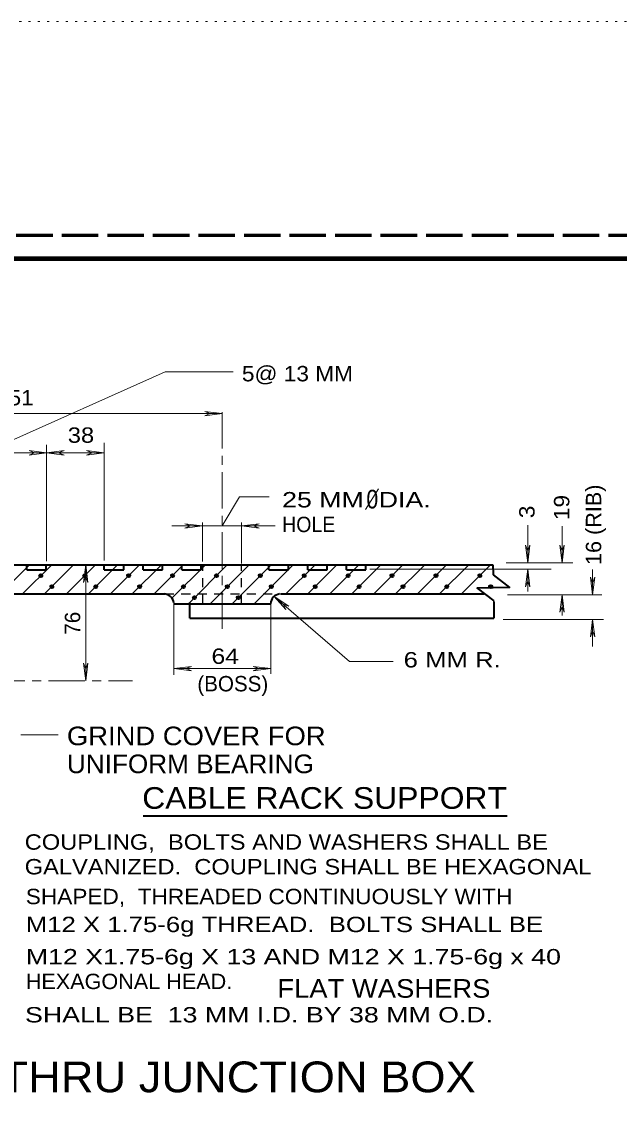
# Model space of a CAD drawing. Extents: x 312583 to 312854, y 144419 to 144597.
# Drawn here: x 312769.2 to 312798.7, y 144543.4 to 144596.8 of the extents above; entities that cross this region are included whole.
import ezdxf
from ezdxf.enums import TextEntityAlignment as Align

# ---------------------------------------------------------------- set-up
doc = ezdxf.new("R2010")
doc.units = 0
doc.header["$LTSCALE"] = 0.3
doc.header["$PDMODE"] = 32
doc.header["$PDSIZE"] = 0.15
for name, pattern in [('DOTTED', [1.5, 0.3, -1.2]), ('LONG_DASH_SHORT_DASH', [9.9, 6, -1.2, 1.5, -1.2]), ('LONG_DASHED', [7.5, 6, -1.5]), ('SHORT_DASHED', [2.7, 1.5, -1.2])]:
    doc.linetypes.add(name, pattern=pattern)
for name, color, linetype, lineweight in [('1', 7, 'Continuous', 40), ('2', 7, 'Continuous', 13), ('63', 7, 'DOTTED', 13)]:
    doc.layers.add(name, color=color, linetype=linetype, lineweight=lineweight)

msp = doc.modelspace()

# ---------------------------------------------------------------- linework, layer by layer
at = {"layer": '1', "linetype": 'LONG_DASHED', "lineweight": 60}
msp.add_line((312851.75, 144586.2246), (312583.526, 144586.2246), dxfattribs=at)
at = {"layer": '1', "lineweight": 13}
for p, q in [((312767.5099, 144575.5592), (312776.3113, 144579.4769)), ((312778.1436, 144571.8716), (312776.6333, 144571.8716)), ((312768.1769, 144568.5136), (312769.6106, 144569.9472)), ((312769.2426, 144568.4982), (312770.6993, 144569.9472)), ((312770.3313, 144568.4982), (312771.7803, 144569.9472)), ((312771.4199, 144568.5059), (312772.8613, 144569.9472)), ((312772.5009, 144568.5059), (312773.9499, 144569.9472)), ((312773.5896, 144568.5059), (312775.0309, 144569.9472)), ((312774.6783, 144568.5136), (312776.1196, 144569.9472)), ((312775.7669, 144568.5136), (312777.2006, 144569.9472)), ((312776.6563, 144568.3219), (312778.2893, 144569.9472)), ((312777.4843, 144568.0612), (312779.3703, 144569.9472)), ((312778.5576, 144568.0536), (312780.4513, 144569.9472)), ((312779.6386, 144568.0459), (312781.5399, 144569.9472)), ((312780.7119, 144568.0382), (312782.6209, 144569.9472)), ((312782.2683, 144568.5136), (312783.7096, 144569.9472)), ((312783.3493, 144568.5136), (312784.7906, 144569.9472)), ((312784.4379, 144568.5136), (312785.8793, 144569.9472)), ((312785.5189, 144568.5136), (312786.9603, 144569.9472)), ((312786.6076, 144568.5136), (312788.0413, 144569.9472)), ((312787.6886, 144568.5136), (312789.1299, 144569.9472)), ((312788.7696, 144568.5136), (312790.2109, 144569.9472)), ((312789.8583, 144568.5136), (312791.2996, 144569.9472)), ((312790.9393, 144568.5136), (312792.3806, 144569.9472)), ((312793.1473, 144570.0546), (312796.4516, 144570.0546))]:
    msp.add_line(p, q, dxfattribs=at)
at = {"layer": '1'}
for p, q in [((312769.4649, 144569.7096), (312769.4649, 144569.9472)), ((312770.4233, 144569.7096), (312770.4233, 144569.9472)), ((312773.2983, 144569.7096), (312773.2983, 144569.9472)), ((312774.2566, 144569.7096), (312774.2566, 144569.9472)), ((312775.2149, 144569.7096), (312775.2149, 144569.9472)), ((312776.1733, 144569.7096), (312776.1733, 144569.9472)), ((312777.1316, 144569.7096), (312777.1316, 144569.9472)), ((312778.0899, 144569.7096), (312778.0899, 144569.9472)), ((312781.4326, 144569.7096), (312781.4326, 144569.9472)), ((312782.3909, 144569.7096), (312782.3909, 144569.9472)), ((312783.3493, 144569.7096), (312783.3493, 144569.9472)), ((312784.3076, 144569.7096), (312784.3076, 144569.9472)), ((312785.2659, 144569.7096), (312785.2659, 144569.9472)), ((312786.2243, 144569.7096), (312786.2243, 144569.9472)), ((312792.4956, 144569.9472), (312792.5033, 144569.4566)), ((312777.5303, 144567.3176), (312777.5303, 144568.0919)), ((312792.5339, 144568.1456), (312792.5493, 144567.3176))]:
    msp.add_line(p, q, dxfattribs=at)
at = {"layer": '1', "lineweight": 158}
msp.add_lwpolyline([(312616.5, 144423.1446), (312616.5, 144585.0846), (312849, 144585.0846)], dxfattribs=at)
at = {"layer": '1'}
for p in [(312770.1626, 144569.4182), (312772.3323, 144569.4182), (312774.5019, 144569.4182), (312776.6716, 144569.4182), (312778.8413, 144569.4182), (312781.0033, 144569.4182), (312783.1729, 144569.4182), (312785.3426, 144569.4182), (312787.5123, 144569.4182), (312789.6819, 144569.4182), (312791.8516, 144569.4182), (312770.7069, 144568.8739), (312772.8766, 144568.8739), (312775.0463, 144568.8739), (312777.2083, 144568.8739), (312779.3779, 144568.8739), (312781.5476, 144568.8739), (312783.7173, 144568.8739), (312785.8869, 144568.8739), (312788.0566, 144568.8739), (312790.2186, 144568.8739), (312792.3883, 144568.8739), (312777.7526, 144568.3296), (312779.9223, 144568.3296)]:
    msp.add_point(p, dxfattribs=at)
at = {"layer": '2'}
for p, q in [((312779.6616, 144579.4769), (312776.3113, 144579.4769)), ((312760.2113, 144577.4222), (312779.1249, 144577.4222)), ((312778.2586, 144577.5296), (312778.5346, 144577.4222)), ((312779.1249, 144577.4222), (312778.2586, 144577.5296)), ((312778.2586, 144577.3149), (312778.5346, 144577.4222)), ((312779.1249, 144577.4222), (312778.2586, 144577.3149)), ((312770.4463, 144570.1236), (312770.4463, 144575.8736)), ((312773.2906, 144570.1619), (312773.2906, 144575.9809)), ((312765.7083, 144575.4826), (312770.4463, 144575.4826)), ((312769.5799, 144575.5899), (312769.8559, 144575.4826)), ((312770.4463, 144575.4826), (312769.5799, 144575.5899)), ((312769.5799, 144575.3752), (312769.8559, 144575.4826)), ((312770.4463, 144575.4826), (312769.5799, 144575.3752)), ((312770.4463, 144575.4826), (312771.3126, 144575.5899)), ((312770.4463, 144575.4826), (312773.2906, 144575.4826)), ((312770.4463, 144575.4826), (312771.3126, 144575.3752)), ((312771.3126, 144575.5899), (312771.0366, 144575.4826)), ((312771.3126, 144575.3752), (312771.0366, 144575.4826)), ((312772.4243, 144575.5899), (312772.7003, 144575.4826)), ((312773.2906, 144575.4826), (312772.4243, 144575.5899)), ((312772.4243, 144575.3752), (312772.7003, 144575.4826)), ((312773.2906, 144575.4826), (312772.4243, 144575.3752)), ((312786.2087, 144572.6833), (312786.845, 144573.7107)), ((312777.2773, 144571.9789), (312777.5533, 144571.8716)), ((312778.1436, 144571.8716), (312777.2773, 144571.9789)), ((312778.1436, 144570.1082), (312778.1436, 144572.0479)), ((312780.0833, 144570.0162), (312780.0833, 144572.0479)), ((312780.0833, 144571.8716), (312780.9496, 144571.9789)), ((312780.9496, 144571.9789), (312780.6736, 144571.8716)), ((312794.2206, 144570.0546), (312794.2206, 144571.9089)), ((312777.2773, 144571.7642), (312777.5533, 144571.8716)), ((312778.1436, 144571.8716), (312777.2773, 144571.7642)), ((312778.1436, 144571.8716), (312780.0833, 144571.8716)), ((312780.0833, 144571.8716), (312781.7393, 144571.8716)), ((312780.0833, 144571.8716), (312780.9496, 144571.7642)), ((312780.9496, 144571.7642), (312780.6736, 144571.8716)), ((312795.9149, 144570.0546), (312795.9149, 144571.8557)), ((312794.1133, 144570.9209), (312794.2206, 144570.6449)), ((312794.2206, 144570.0546), (312794.1133, 144570.9209)), ((312794.3279, 144570.9209), (312794.2206, 144570.6449)), ((312794.2206, 144570.0546), (312794.3279, 144570.9209)), ((312795.8076, 144570.9209), (312795.9149, 144570.6449)), ((312795.9149, 144570.0546), (312795.8076, 144570.9209)), ((312796.0223, 144570.9209), (312795.9149, 144570.6449)), ((312795.9149, 144570.0546), (312796.0223, 144570.9209)), ((312772.3783, 144569.9472), (312772.2709, 144569.0809)), ((312772.3783, 144569.9472), (312772.3783, 144564.2202)), ((312772.3783, 144569.9472), (312772.4856, 144569.0809)), ((312772.2709, 144569.0809), (312772.3783, 144569.3569)), ((312772.4856, 144569.0809), (312772.3783, 144569.3569)), ((312786.4236, 144569.7326), (312795.3706, 144569.7326)), ((312794.2206, 144569.7326), (312794.1133, 144568.8662)), ((312794.2206, 144568.6362), (312794.2206, 144569.7326)), ((312794.2206, 144569.7326), (312794.3279, 144568.8662)), ((312797.3103, 144569.3416), (312797.4176, 144569.0656)), ((312797.4176, 144568.4752), (312797.3103, 144569.3416)), ((312797.4176, 144568.4752), (312797.4176, 144569.7172)), ((312797.5249, 144569.3416), (312797.4176, 144569.0656)), ((312797.4176, 144568.4752), (312797.5249, 144569.3416)), ((312794.1133, 144568.8662), (312794.2206, 144569.1422)), ((312794.3279, 144568.8662), (312794.2206, 144569.1422)), ((312781.6856, 144568.3909), (312782.2683, 144567.7392)), ((312781.6856, 144568.3909), (312782.4139, 144567.9002)), ((312793.2163, 144568.4752), (312797.8853, 144568.4752)), ((312795.9149, 144568.4752), (312795.8076, 144567.6089)), ((312795.9149, 144567.4402), (312795.9149, 144568.4752)), ((312795.9149, 144568.4752), (312796.0223, 144567.6089)), ((312776.7329, 144568.0689), (312776.7329, 144564.5192)), ((312781.5169, 144568.0306), (312781.5169, 144564.5576)), ((312782.2683, 144567.7392), (312782.1303, 144567.9999)), ((312782.4139, 144567.9002), (312782.1303, 144567.9999)), ((312795.8076, 144567.6089), (312795.9149, 144567.8849)), ((312796.0223, 144567.6089), (312795.9149, 144567.8849)), ((312793.0016, 144567.2562), (312797.9619, 144567.2562)), ((312797.4176, 144567.2562), (312797.3103, 144566.3899)), ((312797.4176, 144567.2562), (312797.5249, 144566.3899)), ((312797.4176, 144565.9146), (312797.4176, 144567.2562)), ((312797.3103, 144566.3899), (312797.4176, 144566.6659)), ((312797.5249, 144566.3899), (312797.4176, 144566.6659)), ((312772.2709, 144565.0866), (312772.3783, 144564.8106)), ((312772.3783, 144564.2202), (312772.2709, 144565.0866)), ((312772.4856, 144565.0866), (312772.3783, 144564.8106)), ((312772.3783, 144564.2202), (312772.4856, 144565.0866)), ((312776.7329, 144564.8259), (312777.5993, 144564.9332)), ((312776.7329, 144564.8259), (312781.5169, 144564.8259)), ((312776.7329, 144564.8259), (312777.5993, 144564.7186)), ((312777.5993, 144564.9332), (312777.3233, 144564.8259)), ((312777.5993, 144564.7186), (312777.3233, 144564.8259)), ((312780.6506, 144564.9332), (312780.9266, 144564.8259)), ((312781.5169, 144564.8259), (312780.6506, 144564.9332)), ((312780.6506, 144564.7186), (312780.9266, 144564.8259)), ((312781.5169, 144564.8259), (312780.6506, 144564.7186)), ((312769.1813, 144561.5446), (312771.0136, 144561.5446))]:
    msp.add_line(p, q, dxfattribs=at)
at = {"layer": '2', "linetype": 'LONG_DASH_SHORT_DASH'}
for p, q in [((312779.1249, 144566.7886), (312779.1249, 144577.7059)), ((312755.6879, 144564.2202), (312774.6859, 144564.2202))]:
    msp.add_line(p, q, dxfattribs=at)
at = {"layer": '2', "linetype": 'SHORT_DASHED', "lineweight": 25}
for p, q in [((312778.1666, 144568.0306), (312778.1666, 144569.9472)), ((312780.0833, 144568.0306), (312780.0833, 144569.9472)), ((312776.2883, 144568.5136), (312782.0306, 144568.5136))]:
    msp.add_line(p, q, dxfattribs=at)
at = {"layer": '2', "lineweight": 40}
for p, q in [((312769.4649, 144569.7096), (312770.4233, 144569.7096)), ((312773.2983, 144569.7096), (312774.2566, 144569.7096)), ((312775.2149, 144569.7096), (312776.1733, 144569.7096)), ((312777.1316, 144569.7096), (312778.0899, 144569.7096)), ((312781.4326, 144569.7096), (312782.3909, 144569.7096)), ((312783.3493, 144569.7096), (312784.3076, 144569.7096)), ((312785.2659, 144569.7096), (312786.2243, 144569.7096)), ((312762.7949, 144568.5136), (312776.2883, 144568.5136)), ((312782.0306, 144568.5136), (312792.0586, 144568.5136)), ((312776.7329, 144568.0306), (312781.5246, 144568.0306)), ((312777.5303, 144567.3176), (312792.5493, 144567.3176))]:
    msp.add_line(p, q, dxfattribs=at)
at = {"layer": '2', "lineweight": 35}
msp.add_line((312775.213, 144557.5445), (312793.199, 144557.5445), dxfattribs=at)
at = {"layer": '2'}
for points in [[(312779.1249, 144571.8716), (312779.9759, 144573.3052), (312781.4479, 144573.3052)], [(312787.5659, 144565.1786), (312785.4116, 144565.1786), (312781.6856, 144568.3909)]]:
    msp.add_lwpolyline(points, dxfattribs=at)
at = {"layer": '2', "lineweight": 40}
for points in [[(312760.1959, 144568.0306), (312760.1959, 144569.9472), (312792.4956, 144569.9472)], [(312792.5033, 144569.4566), (312793.3159, 144568.8356), (312791.7213, 144568.8049), (312792.5339, 144568.1762)]]:
    msp.add_lwpolyline(points, dxfattribs=at)
for centre, start, end in [((312776.2339, 144568.0118), 6.36433, 88.1598), ((312782.013, 144568.0146), 96.36433, 178.1598)]:
    msp.add_arc(centre, 0.4982, start, end, dxfattribs=at)
at = {"layer": '63'}
msp.add_line((312601.2, 144596.7846), (312853.5, 144596.7846), dxfattribs=at)

# ---------------------------------------------------------------- texts
at = {"layer": '2'}
for s, height, width, p in [('5@ 13 MM', 0.76, 1.1, (312780.097, 144579.014)), ('251 ', 0.76, 1.1, (312767.9459, 144577.8295)), ('38 ', 0.76, 1.15, (312771.496, 144575.9782)), ('25 MM  DIA.', 0.76, 1.3, (312782.0824, 144572.7859)), ('HOLE', 0.76, 0.95, (312782.0824, 144571.5659)), ('64 ', 0.76, 1.2, (312778.5928, 144565.0568)), ('6 MM R.', 0.76, 1.25, (312788.0854, 144564.8805)), ('GRIND COVER FOR', 0.92, 1.1, (312771.4506, 144561.0386)), ('UNIFORM BEARING', 0.92, 1.05, (312771.4506, 144559.6586)), ('COUPLING,  BOLTS AND WASHERS SHALL BE', 0.76, 1.15, (312769.3653, 144555.8779)), ('GALVANIZED.  COUPLING SHALL BE HEXAGONAL', 0.76, 1.15, (312769.3653, 144554.6579)), ('SHAPED,  THREADED CONTINUOUSLY WITH', 0.76, 1.1, (312769.4189, 144553.1869)), ('M12 X 1.75-6g THREAD.  BOLTS SHALL BE', 0.76, 1.25, (312769.4189, 144551.8069)), ('M12 X1.75-6g X 13 AND M12 X 1.75-6g x 40', 0.76, 1.3, (312769.4189, 144550.2122)), ('HEXAGONAL HEAD.', 0.76, 1.05, (312769.4189, 144548.9922)), (' FLAT WASHERS', 0.92, 1.1, (312781.4709, 144548.5649)), ('SHALL BE  13 MM I.D. BY 38 MM O.D.', 0.76, 1.3, (312769.3806, 144547.3449))]:
    msp.add_text(s, height=height, dxfattribs=dict(at, width=width)).set_placement(p)
for s, height, width, p in [('0', 0.92, 0.85, (312786.5383, 144572.737)), ('CABLE RACK SUPPORT', 1.07, 1.1, (312784.1797, 144557.8981)), ('SECTION THRU JUNCTION BOX', 1.52, 1.1, (312774.6286, 144543.8947))]:
    msp.add_text(s, height=height, dxfattribs=dict(at, width=width)).set_placement(p, align=Align.CENTER)
for s, width, p in [('16 (RIB)', 1.05, (312797.8468, 144569.9423)), ('19 ', 1.1, (312796.2722, 144572.1583)), ('3 ', 1.1, (312794.5551, 144572.253))]:
    msp.add_text(s, height=0.76, rotation=90, dxfattribs=dict(at, width=width)).set_placement(p)
msp.add_text('76', height=0.76, rotation=90, dxfattribs=at).set_placement((312772.1065, 144566.5006))
msp.add_text('(BOSS)', height=0.76, dxfattribs=at).set_placement((312777.8957, 144563.6988))

doc.saveas('drawing.dxf')
